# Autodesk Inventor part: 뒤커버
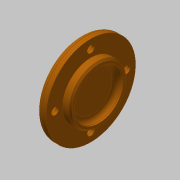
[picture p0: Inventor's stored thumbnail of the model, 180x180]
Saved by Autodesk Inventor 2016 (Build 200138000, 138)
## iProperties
Created: 2019-06
Part Number: 뒤커버
Material: 알루미늄 6061
Document SubType Name: Modeling
Designer: mduedu
Density: 2.71 g/cm^3
Appearance: 주황색
Mass: 40.7816 g
Surface Area: 66.9571 cm^2
Volume: 15.0486 cm^3
Author: mduedu
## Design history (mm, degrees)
sketch "스케치1"
  geometry: L1 (0, 0)-(-5, 0); L2 (-5, 0)-(-5, 17.5); L3 (-5, 17.5)-(0, 17.5); L4 (0, 17.5)-(0, 0); L5 (-5, 0)-(-11, 0); L6 (-11, 0)-(-11, 27.5); L7 (-11, 27.5)-(-5, 27.5); L8 (-5, 27.5)-(-5, 0)
  constraints: 16 end point, 4 parallel, 2 horizontal, 2 perpendicular
  dimensions: "d0" = 11 distance between parallel lines of L4 L6; "d2" = 5 distance of L2.end L3.end; "d3" = 55 diameter of L7 L5; "d4" = 35 diameter of L3 L1
revolve "회전1" sketch "스케치1" stored, may be unused: angle "d5" = 90 deg
sketch "스케치2"
  geometry: C1 r 15 at (0, 0); 1 further point
  constraints: 1 centre point, 1 coincident
  dimensions: "d6" = 30 diameter of C1
extrude "돌출1" cut sketch "스케치2" distance "d7" = 4; taper "d8" = 0 deg
fillet "모깎기1" dims "d9" = 3
fillet "모깎기2" dims "d10" = 3
chamfer "모따기1" distance "d11" = 1; stored, may be unused: second distance "d12" = 2, angle "d13" = 45 deg
sketch "스케치3" dims "d14" = 44
  geometry: 3 further points
  constraints: 2 vertical alignment, 1 coincident, 2 other
hole "구멍1" sketch "스케치3" at (0, 22) diameter "d15" = 4.5; stored, may be unused: countersink angle "d19" = 90 deg, drill point angle "d21" = 118 deg; dims "d16" = 6, "d17" = 8, "d18" = 4.4, "d20" = 8
node "솔리드1"
pattern_circular "원형 패턴1" dims angle "d23" = 360 deg
